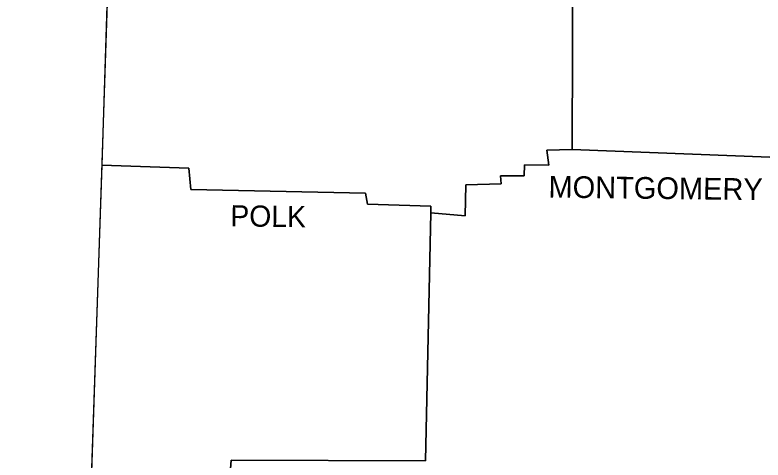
# Model space of a CAD drawing. Extents: x 1370567 to 1373900, y 377514 to 379648.
# Drawn here: x 1373164.5 to 1373319.4, y 379054.3 to 379146.4 of the extents above; entities that cross this region are included whole.
import ezdxf

# ---------------------------------------------------------------- set-up
doc = ezdxf.new("R2010")
doc.units = 0
doc.layers.add('Survey Names', color=7, linetype='Continuous')
doc.layers.add('Survey Symbols', color=7, linetype='Continuous')

msp = doc.modelspace()

# ---------------------------------------------------------------- linework, layer by layer
at = {"layer": 'Survey Names'}
for points in [[(1373164.5, 379398.98), (1373186.12, 379225.46), (1373176.72, 378942.19)], [(1373280.03, 379161.31), (1373279.88, 379118.54), (1373274.66, 379118.44), (1373275.08, 379115.3), (1373270.06, 379115.41), (1373269.96, 379113.11), (1373265.05, 379113.11), (1373265.16, 379111.44), (1373257.85, 379111.23), (1373257.74, 379104.86), (1373250.64, 379105.49), (1373249.5, 379054.12), (1373209.3, 379054.22), (1373208.36, 379042.32), (1373209.82, 379041.28), (1373209.71, 379027.91), (1373179.61, 379029.24)], [(1373320.81, 379116.97), (1373279.88, 379118.54)], [(1373182.46, 379115.3), (1373200.53, 379114.68), (1373200.94, 379110.29), (1373237.07, 379109.56), (1373237.49, 379107.26), (1373250.64, 379106.85), (1373250.64, 379105.49)]]:
    msp.add_lwpolyline(points, dxfattribs=at)
at = {"layer": 'Survey Symbols'}
for p, q in [((1373280.03, 379161.31), (1373279.88, 379118.54)), ((1373183.56, 379148.38), (1373182.46, 379115.3)), ((1373279.88, 379118.54), (1373320.81, 379116.97)), ((1373320.81, 379116.97), (1373279.88, 379118.54)), ((1373182.46, 379115.3), (1373179.61, 379029.24)), ((1373270.06, 379115.41), (1373269.96, 379113.11)), ((1373275.08, 379115.3), (1373270.06, 379115.41)), ((1373257.85, 379111.23), (1373257.74, 379104.86)), ((1373265.16, 379111.44), (1373257.85, 379111.23))]:
    msp.add_line(p, q, dxfattribs=at)
for points in [[(1373250.64, 379105.49), (1373257.74, 379104.86), (1373257.85, 379111.23), (1373265.16, 379111.44), (1373265.05, 379113.11), (1373269.96, 379113.11), (1373270.06, 379115.41), (1373275.08, 379115.3), (1373274.66, 379118.44), (1373279.88, 379118.54), (1373280.03, 379161.31)], [(1373279.88, 379118.54), (1373274.66, 379118.44), (1373275.08, 379115.3)], [(1373250.64, 379105.49), (1373250.64, 379106.85), (1373237.49, 379107.26), (1373237.07, 379109.56), (1373200.94, 379110.29), (1373200.53, 379114.68), (1373182.46, 379115.3)], [(1373182.46, 379115.3), (1373200.53, 379114.68), (1373200.94, 379110.29), (1373237.07, 379109.56), (1373237.49, 379107.26)], [(1373269.96, 379113.11), (1373265.05, 379113.11), (1373265.16, 379111.44)], [(1373237.49, 379107.26), (1373250.64, 379106.85), (1373250.64, 379105.49)], [(1373179.61, 379029.24), (1373209.71, 379027.91), (1373209.82, 379041.28), (1373208.36, 379042.32), (1373209.3, 379054.22), (1373249.5, 379054.12), (1373250.64, 379105.49)], [(1373257.74, 379104.86), (1373250.64, 379105.49), (1373249.5, 379054.12)]]:
    msp.add_lwpolyline(points, dxfattribs=at)

# ---------------------------------------------------------------- texts
at = {"layer": 'Survey Names'}
for s, height, rotation, p in [('MONTGOMERY', 4.49, 359.2944, (1373274.97, 379108.62)), ('POLK', 4.384, 359.2152, (1373209.09, 379102.67))]:
    msp.add_text(s, height=height, rotation=rotation, dxfattribs=at).set_placement(p)

doc.saveas('drawing.dxf')
